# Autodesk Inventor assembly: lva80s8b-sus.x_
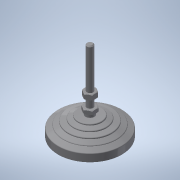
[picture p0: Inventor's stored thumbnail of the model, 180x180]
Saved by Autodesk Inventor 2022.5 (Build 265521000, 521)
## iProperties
Part Number: lva80s8b-sus.x_
Material: 一般
Document SubType Name: Assembly
Designer: ImaoCorp
Sending System: SOLIDWORKS 2017-2017317
MC: AMD64
MC_MODEL: Intel64 Family 6 Model 60 Stepping 3, GenuineIntel
OS: Windows_NT
FRU: Parasolid Version 29.0, build 201,  4-17-2017
FORMAT: text
GUISE: transmit
KEY: lva80s8b-sus
FILE: lva80s8b-sus.x_t
DATE: Mon Jul 01 18:10:25 2019
Author: ImaoCorp
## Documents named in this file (3)
- X:\14_SW2022-Inv2022\00_全2023-1023新製品(TCC)まで\l\lva80s8b-sus\LVA80S8B-SUS.iam
- X:\14_SW2022-Inv2022\00_全2023-1023新製品(TCC)まで\l\lva80s8b-sus\lva80s8b-sus_01.ipt
- X:\14_SW2022-Inv2022\00_全2023-1023新製品(TCC)まで\l\lva80s8b-sus\lva80s8b-sus_02.ipt
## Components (2 placed, 2 different names)
1. lva80s8b-sus_01
2. lva80s8b-sus_02
